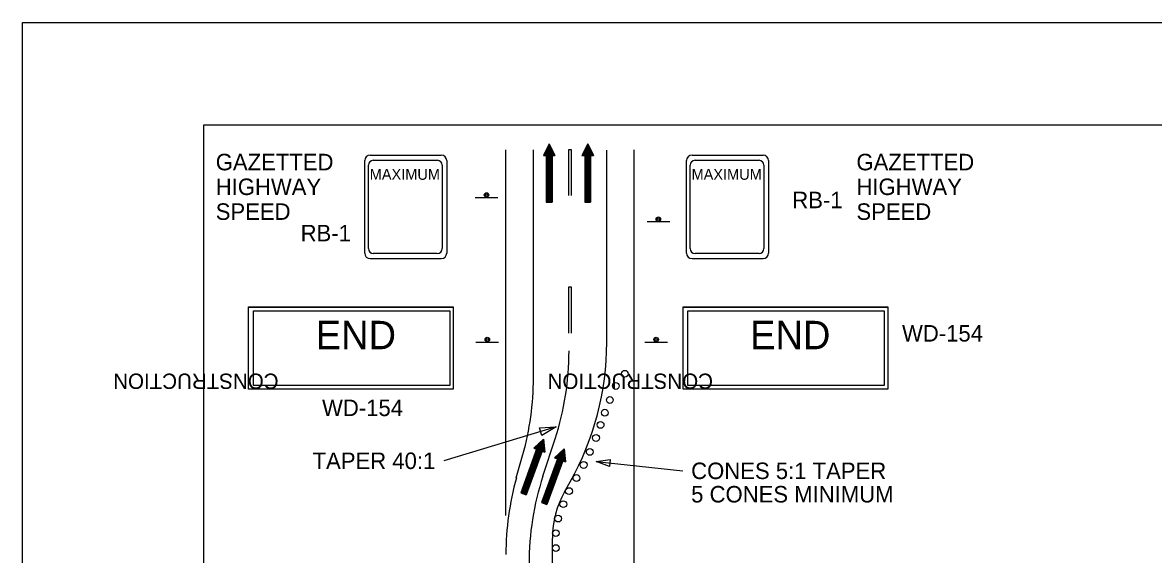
# Model space of a CAD drawing. Extents: x 2170 to 2386, y 134 to 413.
# Drawn here: x 2169.6 to 2288.9, y 356.6 to 412.8 of the extents above; entities that cross this region are included whole.
import ezdxf

# ---------------------------------------------------------------- set-up
doc = ezdxf.new("R2010")
doc.units = 0
for name, color, linetype in [('Level 10', 7, 'Continuous'), ('Level 2', 7, 'Continuous'), ('Level 20', 7, 'Continuous'), ('Level 4', 7, 'Continuous'), ('Level 44', 7, 'Continuous'), ('Level 60', 7, 'Continuous')]:
    doc.layers.add(name, color=color, linetype=linetype)

# ---------------------------------------------------------------- blocks, each defined once
blk = doc.blocks.new('END')
at = {"layer": 'Level 2'}
for points in [[(0, 8.676), (21.598, 8.676), (21.598, 0), (0, 0)], [(0.511, 8.287), (21.224, 8.287), (21.224, 0.397), (0.511, 0.397)]]:
    blk.add_lwpolyline(points, close=True, dxfattribs=at)
at = {"layer": 'Level 44'}
for s, height, rotation, p in [('END', 3, 359.99999, (7.085, 4.219)), ('CONSTRUCTION', 1.62, 179.99999, (3.164, 1.653))]:
    blk.add_text(s, height=height, rotation=rotation, dxfattribs=at).set_placement(p)

msp = doc.modelspace()

# ---------------------------------------------------------------- linework, layer by layer
at = {"layer": 'Level 10'}
for p, q in [((2225.19, 399.95), (2224.58, 398.72)), ((2225.11, 399.8), (2225.11, 393.81)), ((2225.19, 399.95), (2225.19, 393.81)), ((2225.19, 399.95), (2225.8, 398.72)), ((2225.27, 399.8), (2225.27, 393.81)), ((2229.26, 399.95), (2228.64, 398.72)), ((2229.18, 399.8), (2229.18, 393.81)), ((2229.26, 399.95), (2229.26, 393.81)), ((2229.26, 399.95), (2229.87, 398.72)), ((2229.33, 399.8), (2229.33, 393.81)), ((2223.52, 375.22), (2223.52, 399.31)), ((2224.58, 398.72), (2224.88, 398.72)), ((2224.65, 398.88), (2224.65, 398.72)), ((2224.73, 399.03), (2224.73, 398.72)), ((2224.81, 399.18), (2224.81, 398.72)), ((2224.88, 399.34), (2224.88, 393.81)), ((2224.88, 398.72), (2224.88, 393.81)), ((2224.96, 399.49), (2224.96, 393.81)), ((2225.03, 399.64), (2225.03, 393.81)), ((2225.34, 399.64), (2225.34, 393.81)), ((2225.42, 399.49), (2225.42, 393.81)), ((2225.5, 399.34), (2225.5, 393.81)), ((2225.5, 398.72), (2225.5, 393.81)), ((2225.5, 398.72), (2225.8, 398.72)), ((2225.57, 399.18), (2225.57, 398.72)), ((2225.65, 399.03), (2225.65, 398.72)), ((2225.73, 398.88), (2225.73, 398.72)), ((2228.64, 398.72), (2228.95, 398.72)), ((2228.72, 398.88), (2228.72, 398.72)), ((2228.8, 399.03), (2228.8, 398.72)), ((2228.87, 399.18), (2228.87, 398.72)), ((2228.95, 399.34), (2228.95, 393.81)), ((2228.95, 398.72), (2228.95, 393.81)), ((2229.03, 399.49), (2229.03, 393.81)), ((2229.1, 399.64), (2229.1, 393.81)), ((2229.41, 399.64), (2229.41, 393.81)), ((2229.49, 399.49), (2229.49, 393.81)), ((2229.56, 399.34), (2229.56, 393.81)), ((2229.56, 398.72), (2229.56, 393.81)), ((2229.56, 398.72), (2229.87, 398.72)), ((2229.64, 399.18), (2229.64, 398.72)), ((2229.72, 399.03), (2229.72, 398.72)), ((2229.79, 398.88), (2229.79, 398.72)), ((2231.26, 378.98), (2231.26, 399.28)), ((2224.88, 393.81), (2225.5, 393.81)), ((2228.95, 393.81), (2229.56, 393.81)), ((2225.94, 370.07), (2214.07, 366.49)), ((2224.57, 368.77), (2222.47, 363)), ((2224.57, 368.77), (2223.57, 367.83)), ((2224.53, 364.88), (2225.81, 368.82)), ((2224.57, 368.77), (2224.73, 367.41)), ((2224.07, 368.3), (2222.18, 363.11)), ((2223.86, 367.72), (2222.18, 363.11)), ((2224.2, 368.42), (2222.26, 363.08)), ((2224.32, 368.54), (2222.33, 363.06)), ((2224.45, 368.65), (2222.4, 363.03)), ((2224.59, 368.6), (2222.54, 362.98)), ((2224.61, 368.43), (2222.62, 362.95)), ((2224.63, 368.26), (2222.69, 362.93)), ((2224.65, 368.09), (2222.76, 362.9)), ((2223.57, 367.83), (2223.86, 367.72)), ((2223.7, 367.94), (2223.65, 367.8)), ((2223.82, 368.06), (2223.72, 367.78)), ((2223.95, 368.18), (2223.79, 367.75)), ((2224.67, 367.92), (2224.51, 367.49)), ((2224.69, 367.75), (2224.58, 367.46)), ((2226.63, 367.62), (2224.59, 362)), ((2226.76, 367.74), (2224.66, 361.97)), ((2224.71, 367.58), (2224.66, 367.43)), ((2226.78, 367.57), (2224.73, 361.95)), ((2226.76, 367.74), (2225.76, 366.79)), ((2226.76, 367.74), (2226.91, 366.38)), ((2221.72, 364.68), (2222.41, 367.15)), ((2224.44, 367.51), (2222.76, 362.9)), ((2226.26, 367.27), (2224.37, 362.08)), ((2226.05, 366.69), (2224.37, 362.08)), ((2224.44, 367.51), (2224.73, 367.41)), ((2226.39, 367.38), (2224.44, 362.05)), ((2226.51, 367.5), (2224.51, 362.03)), ((2226.8, 367.4), (2224.8, 361.92)), ((2226.82, 367.23), (2224.88, 361.89)), ((2226.84, 367.06), (2224.95, 361.87)), ((2226.63, 366.48), (2224.95, 361.87)), ((2225.76, 366.79), (2226.05, 366.69)), ((2225.89, 366.91), (2225.83, 366.77)), ((2226.01, 367.03), (2225.91, 366.74)), ((2226.14, 367.15), (2225.98, 366.72)), ((2226.63, 366.48), (2226.91, 366.38)), ((2226.86, 366.89), (2226.7, 366.45)), ((2226.88, 366.72), (2226.77, 366.43)), ((2226.9, 366.55), (2226.84, 366.4)), ((2230.13, 366.42), (2239.3, 365.43)), ((2226.82, 363.23), (2227.4, 364.26)), ((2222.18, 363.11), (2222.76, 362.9)), ((2224.37, 362.08), (2224.95, 361.87))]:
    msp.add_line(p, q, dxfattribs=at)
for points in [[(2224.15, 369.98), (2225.94, 370.07), (2224.4, 369.15)], [(2231.54, 365.9), (2230.13, 366.42), (2231.61, 366.63)]]:
    msp.add_lwpolyline(points, close=True, dxfattribs=at)
for centre in [(2233.17, 375.68), (2232.22, 374.39), (2231.59, 372.91), (2231.06, 371.57), (2230.61, 370.28), (2230.13, 368.9), (2229.47, 367.43), (2228.83, 366.05), (2228.83, 366.05), (2228.83, 366.05), (2228.06, 364.67), (2228.06, 364.67), (2228.06, 364.67), (2227.28, 363.29), (2227.28, 363.29), (2227.28, 363.29), (2226.68, 361.91), (2226.12, 360.39), (2225.89, 358.85), (2225.89, 357.27)]:
    msp.add_circle(centre, 0.359, dxfattribs=at)
for centre, radius, start, end in [((2201.26, 378.98), 30, 330.6066, 0), ((2197.28, 378.09), 30, 341.9995, 0), ((2193.52, 375.22), 30, 344.3937, 0), ((2250.62, 356.61), 30, 164.3937, 180), ((2253.06, 355.61), 30, 161.9995, 180), ((2235.53, 358.32), 10, 150.6066, 179.9638)]:
    msp.add_arc(centre, radius, start, end, dxfattribs=at)
at = {"layer": 'Level 2'}
for p, q in [((2227.24, 399.33), (2227.24, 394.49)), ((2227.53, 399.33), (2227.24, 399.33)), ((2227.53, 394.49), (2227.53, 399.33)), ((2227.24, 384.81), (2227.24, 379.98)), ((2227.53, 384.81), (2227.24, 384.81)), ((2227.53, 379.98), (2227.53, 384.81))]:
    msp.add_line(p, q, dxfattribs=at)
for points in [[(2193.47, 382.73), (2215.07, 382.73), (2215.07, 374.05), (2193.47, 374.05)], [(2193.98, 382.34), (2214.7, 382.34), (2214.7, 374.44), (2193.98, 374.44)], [(2239.31, 382.73), (2260.91, 382.73), (2260.91, 374.05), (2239.31, 374.05)], [(2239.82, 382.34), (2260.53, 382.34), (2260.53, 374.44), (2239.82, 374.44)]]:
    msp.add_lwpolyline(points, close=True, dxfattribs=at)
at = {"layer": 'Level 20'}
for p, q in [((2220.62, 360.72), (2220.62, 399.31)), ((2234.16, 349.42), (2234.16, 399.31))]:
    msp.add_line(p, q, dxfattribs=at)
at = {"layer": 'Level 4'}
msp.add_line((2225.51, 317.4), (2225.53, 358.33), dxfattribs=at)
at = {"layer": 'Level 44'}
for p, q in [((2206.3, 398.76), (2213.8, 398.76)), ((2240.26, 398.76), (2247.75, 398.76)), ((2205.72, 388.41), (2205.72, 398.18)), ((2206.11, 388.91), (2206.11, 397.7)), ((2206.63, 398.22), (2213.38, 398.22)), ((2213.9, 397.7), (2213.9, 388.91)), ((2214.38, 398.18), (2214.38, 388.41)), ((2239.68, 388.41), (2239.68, 398.18)), ((2240.07, 388.91), (2240.07, 397.7)), ((2240.59, 398.22), (2247.33, 398.22)), ((2247.85, 397.7), (2247.85, 388.91)), ((2248.33, 398.18), (2248.33, 388.41)), ((2217.37, 394.28), (2219.77, 394.28)), ((2235.51, 391.74), (2237.91, 391.74)), ((2205.72, 388.41), (2205.72, 388.41)), ((2206.11, 388.91), (2206.11, 388.91)), ((2213.8, 387.83), (2206.3, 387.83)), ((2213.38, 388.38), (2206.63, 388.38)), ((2239.68, 388.41), (2239.68, 388.41)), ((2240.07, 388.91), (2240.07, 388.91)), ((2247.75, 387.83), (2240.26, 387.83)), ((2247.33, 388.38), (2240.59, 388.38)), ((2217.45, 379.03), (2219.85, 379.03)), ((2235.27, 379.03), (2237.66, 379.03))]:
    msp.add_line(p, q, dxfattribs=at)
for centre, radius in [((2218.58, 394.55), 0.24), ((2218.58, 394.55), 0.12), ((2236.71, 392.01), 0.24), ((2236.71, 392.01), 0.12), ((2218.66, 379.3), 0.24), ((2236.47, 379.3), 0.24), ((2218.66, 379.3), 0.12), ((2236.47, 379.3), 0.12)]:
    msp.add_circle(centre, radius, dxfattribs=at)
for centre, radius, start, end in [((2206.3, 398.18), 0.578, 90, 180), ((2213.8, 398.18), 0.578, 360, 90), ((2240.26, 398.18), 0.578, 90, 180), ((2247.75, 398.18), 0.578, 360, 90), ((2206.63, 397.7), 0.52, 90, 180), ((2213.38, 397.7), 0.52, 360, 90), ((2240.59, 397.7), 0.52, 90, 180), ((2247.33, 397.7), 0.52, 360, 90), ((2206.3, 388.41), 0.578, 180, 270), ((2206.63, 388.9), 0.52, 180, 270), ((2213.38, 388.9), 0.52, 270, 360), ((2213.8, 388.41), 0.578, 270, 360), ((2240.26, 388.41), 0.578, 180, 270), ((2240.59, 388.9), 0.52, 180, 270), ((2247.33, 388.9), 0.52, 270, 360), ((2247.75, 388.41), 0.578, 270, 360)]:
    msp.add_arc(centre, radius, start, end, dxfattribs=at)
at = {"layer": 'Level 60'}
msp.add_line((2169.62, 412.76), (2169.62, 412.76), dxfattribs=at)
for points in [[(2169.62, 412.76), (2385.62, 412.76), (2385.62, 133.76), (2169.62, 133.76)], [(2188.75, 401.95), (2375.62, 401.95), (2375.62, 144.57), (2188.75, 144.57)]]:
    msp.add_lwpolyline(points, close=True, dxfattribs=at)

# ---------------------------------------------------------------- block references
at = {"layer": 'Level 2'}
for p in [(2193.47, 374.05), (2239.31, 374.05)]:
    msp.add_blockref('END', p, dxfattribs=at)

# ---------------------------------------------------------------- texts
at = {"layer": 'Level 10'}
for s, p in [('GAZETTED', (2190, 397.16)), ('GAZETTED', (2257.61, 397.16)), ('HIGHWAY', (2190, 394.55)), ('HIGHWAY', (2257.61, 394.55)), ('RB-1', (2250.84, 393.16)), ('SPEED', (2190, 391.93)), ('SPEED', (2257.61, 391.93)), ('RB-1', (2198.96, 389.66)), ('WD-154', (2262.42, 379.08)), ('WD-154', (2201.22, 371.21)), ('TAPER 40:1', (2200.22, 365.62)), ('CONES 5:1 TAPER', (2240.17, 364.56)), ('5 CONES MINIMUM', (2240.17, 362.09))]:
    msp.add_text(s, height=1.742, dxfattribs=at).set_placement(p)
at = {"layer": 'Level 44'}
for s, height, rotation, p in [('MAXIMUM', 1.147, 360, (2206.25, 396.16)), ('MAXIMUM', 1.147, 360, (2240.21, 396.16)), ('CONSTRUCTION', 1.6202, 180, (2196.63, 375.7)), ('CONSTRUCTION', 1.6202, 180, (2242.47, 375.7))]:
    msp.add_text(s, height=height, rotation=rotation, dxfattribs=at).set_placement(p)

doc.saveas('drawing.dxf')
